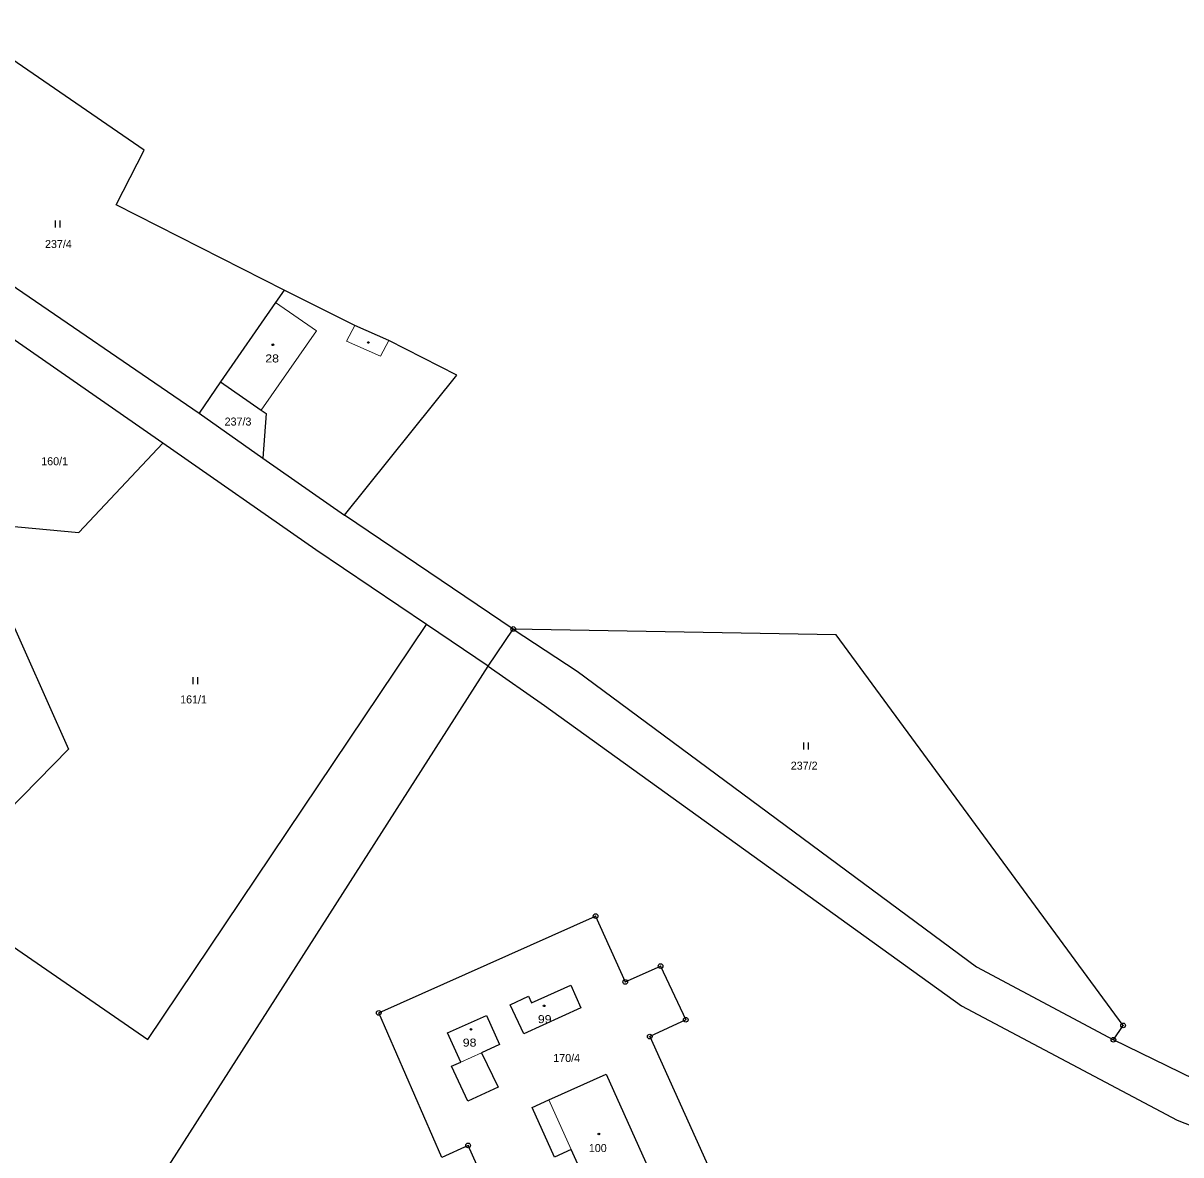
# Model space of a CAD drawing. Extents: x -632162 to -629607, y -1101195 to -1098670.
# Drawn here: x -631672.5 to -631426.6, y -1099752.9 to -1099512.4 of the extents above; entities that cross this region are included whole.
import ezdxf
from ezdxf.enums import TextEntityAlignment as Align

# ---------------------------------------------------------------- set-up
doc = ezdxf.new("R2010")
doc.units = 0
doc.header["$LTSCALE"] = 0.68
for name, color, linetype, lineweight in [('1', 7, 'Continuous', 25), ('3', 7, 'Continuous', 25), ('4', 7, 'Continuous', 13), ('5', 7, 'Continuous', 25), ('8', 7, 'Continuous', 25)]:
    doc.layers.add(name, color=color, linetype=linetype, lineweight=lineweight)
doc.layers.add('2', color=7, linetype='Continuous')

msp = doc.modelspace()

# ---------------------------------------------------------------- linework, layer by layer
at = {"layer": '1'}
for p, q in [((-631707.18, -1099545.97), (-631635.13, -1099595.26)), ((-631642.83, -1099601.66), (-631676.76, -1099578.04)), ((-631573.73, -1099649.04), (-631586.86, -1099640.17))]:
    msp.add_line(p, q, dxfattribs=at)
for points in [[(-631617.07, -1099569.13), (-631652.72, -1099550.98), (-631646.8, -1099539.36), (-631686.1, -1099512.39), (-631688.04, -1099515.48)], [(-631617.07, -1099569.13), (-631618.89, -1099571.76), (-631630.58, -1099588.61)], [(-631604.25, -1099616.92), (-631580.36, -1099587.16), (-631594.87, -1099579.85), (-631602.07, -1099576.67), (-631617.07, -1099569.13)], [(-631630.58, -1099588.61), (-631635.13, -1099595.26), (-631621.59, -1099604.86)], [(-631630.58, -1099588.61), (-631621.92, -1099594.65), (-631620.88, -1099595.34), (-631621.59, -1099604.86), (-631604.25, -1099616.92)], [(-631677.69, -1099624.77), (-631676.66, -1099619.1), (-631660.7, -1099620.6), (-631642.83, -1099601.66)], [(-631586.86, -1099640.17), (-631610.32, -1099624.28), (-631642.83, -1099601.66)], [(-631573.73, -1099649.04), (-631568.4, -1099641.13), (-631604.25, -1099616.92)], [(-631676.68, -1099635.62), (-631662.84, -1099666.69), (-631692.22, -1099696.53)], [(-631692.22, -1099696.53), (-631646.04, -1099728.34), (-631586.86, -1099640.17)], [(-631568.4, -1099641.13), (-631554.84, -1099650.07), (-631470, -1099712.9), (-631440.94, -1099728.4)], [(-631440.94, -1099728.4), (-631438.87, -1099725.35), (-631499.84, -1099642.36), (-631568.4, -1099641.13)], [(-631674.85, -1099808.29), (-631665.24, -1099792.15), (-631573.73, -1099649.04)], [(-631573.73, -1099649.04), (-631561.78, -1099657.37), (-631473.19, -1099721.18), (-631427.36, -1099745.46), (-631262.62, -1099810.08), (-631104.85, -1099904.21), (-631080.72, -1099918.6), (-630227.98, -1100408.08)], [(-631259.83, -1099801.22), (-631423.81, -1099736.81), (-631440.94, -1099728.4)]]:
    msp.add_lwpolyline(points, dxfattribs=at)
for points in [[(-631531.77, -1099724.17), (-631539.42, -1099727.73), (-631522.28, -1099765.74), (-631562.86, -1099784.63), (-631577.99, -1099750.85), (-631583.61, -1099753.43), (-631596.98, -1099722.7), (-631550.92, -1099702.14), (-631544.63, -1099716.13), (-631537.12, -1099712.75)], [(-631566.14, -1099727.17), (-631569.04, -1099720.96), (-631565.14, -1099719.14), (-631564.5, -1099720.56), (-631556.21, -1099716.82), (-631554.03, -1099721.64)], [(-631571.3, -1099729.45), (-631575.15, -1099731.18), (-631571.64, -1099738.48), (-631578.05, -1099741.43), (-631581.5, -1099734.02), (-631579.56, -1099733.15), (-631582.35, -1099726.91), (-631574.09, -1099723.22)], [(-631550.19, -1099764.86), (-631556.14, -1099751.74), (-631559.66, -1099753.34), (-631564.42, -1099742.8), (-631560.84, -1099741.19), (-631548.7, -1099735.73), (-631538.06, -1099759.37)]]:
    msp.add_lwpolyline(points, close=True, dxfattribs=at)
at = {"layer": '3'}
for p, q in [((-631665.671, -1099555.83), (-631665.671, -1099554.33)), ((-631664.67, -1099555.83), (-631664.67, -1099554.33)), ((-631636.391, -1099652.86), (-631636.391, -1099651.36)), ((-631635.39, -1099652.86), (-631635.39, -1099651.36)), ((-631506.671, -1099666.72), (-631506.671, -1099665.22)), ((-631505.67, -1099666.72), (-631505.67, -1099665.22))]:
    msp.add_line(p, q, dxfattribs=at)
at = {"layer": '4'}
for p, q in [((-631610.23, -1099577.75), (-631618.89, -1099571.76)), ((-631610.23, -1099577.75), (-631621.92, -1099594.65)), ((-631602.07, -1099576.67), (-631603.8, -1099579.99)), ((-631596.6, -1099583.17), (-631603.8, -1099579.99)), ((-631594.87, -1099579.85), (-631596.6, -1099583.17)), ((-631579.56, -1099733.15), (-631575.15, -1099731.18)), ((-631556.14, -1099751.74), (-631560.84, -1099741.19))]:
    msp.add_line(p, q, dxfattribs=at)
at = {"layer": '5'}
for centre in [(-631619.4568, -1099580.7292), (-631599.1868, -1099580.2492), (-631561.8568, -1099721.1992), (-631577.3668, -1099726.2092), (-631550.2168, -1099748.4192)]:
    msp.add_circle(centre, 0.175, dxfattribs=at)
at = {"layer": '8'}
for centre, radius in [((-631568.4, -1099641.1299), 0.5), ((-631568.4, -1099641.1299), 0.0303), ((-631550.92, -1099702.1399), 0.5), ((-631550.92, -1099702.1399), 0.0303), ((-631537.12, -1099712.7499), 0.5), ((-631537.12, -1099712.7499), 0.0303), ((-631544.63, -1099716.1299), 0.5), ((-631544.63, -1099716.1299), 0.0303), ((-631596.98, -1099722.6999), 0.5), ((-631596.98, -1099722.6999), 0.0303), ((-631531.77, -1099724.1699), 0.5), ((-631531.77, -1099724.1699), 0.0303), ((-631438.87, -1099725.3499), 0.5), ((-631438.87, -1099725.3499), 0.0303), ((-631539.42, -1099727.7299), 0.5), ((-631539.42, -1099727.7299), 0.0303), ((-631440.94, -1099728.3999), 0.5), ((-631440.94, -1099728.3999), 0.0303), ((-631577.99, -1099750.8499), 0.5), ((-631577.99, -1099750.8499), 0.0303)]:
    msp.add_circle(centre, radius, dxfattribs=at)

# ---------------------------------------------------------------- texts
at = {"layer": '2'}
for s, p in [('237/4', (-631665.02, -1099560.17)), ('237/3', (-631626.87, -1099597.9)), ('160/1', (-631665.82, -1099606.33)), ('161/1', (-631636.31, -1099656.94)), ('237/2', (-631506.62, -1099671.01)), ('170/4', (-631557.06, -1099733.13)), ('100', (-631550.459, -1099752.27))]:
    msp.add_text(s, height=1.7, dxfattribs=at).set_placement(p, align=Align.CENTER)
at = {"layer": '2', "width": 1.15}
for s, p in [('28', (-631619.62, -1099584.49)), ('99', (-631561.73, -1099724.87)), ('98', (-631577.68, -1099729.86))]:
    msp.add_text(s, height=1.7, dxfattribs=at).set_placement(p, align=Align.CENTER)

doc.saveas('drawing.dxf')
